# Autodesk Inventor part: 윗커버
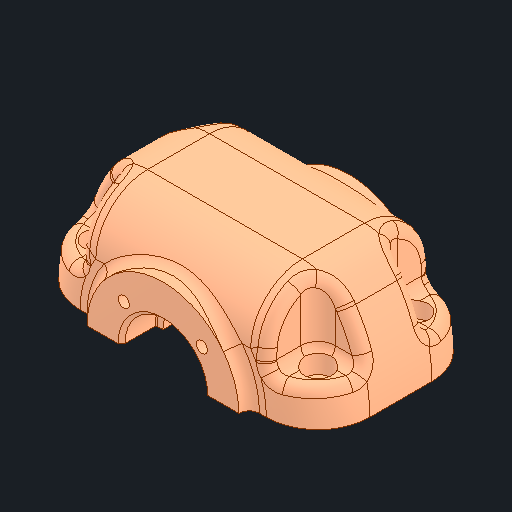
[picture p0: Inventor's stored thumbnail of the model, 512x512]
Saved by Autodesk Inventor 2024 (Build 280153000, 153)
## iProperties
Created: 2024-05
Part Number: 윗커버
Material: 알루미늄 6061
Document SubType Name: Modeling
Designer: kh_501
Density: 2.7 g/cm^3
Appearance: 기본값
Author: jhkim
Sending System: Autodesk Inventor 2025
Preprocessor: ST-DEVELOPER v20
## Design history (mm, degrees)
node "윗커버1"
node "솔리드2"
node "솔리드1"
